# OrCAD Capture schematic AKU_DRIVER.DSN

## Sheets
1 CHARGER: size A4; title: Pb-accu driver - Charger; rev: A; note: Pb-accu_driver_01
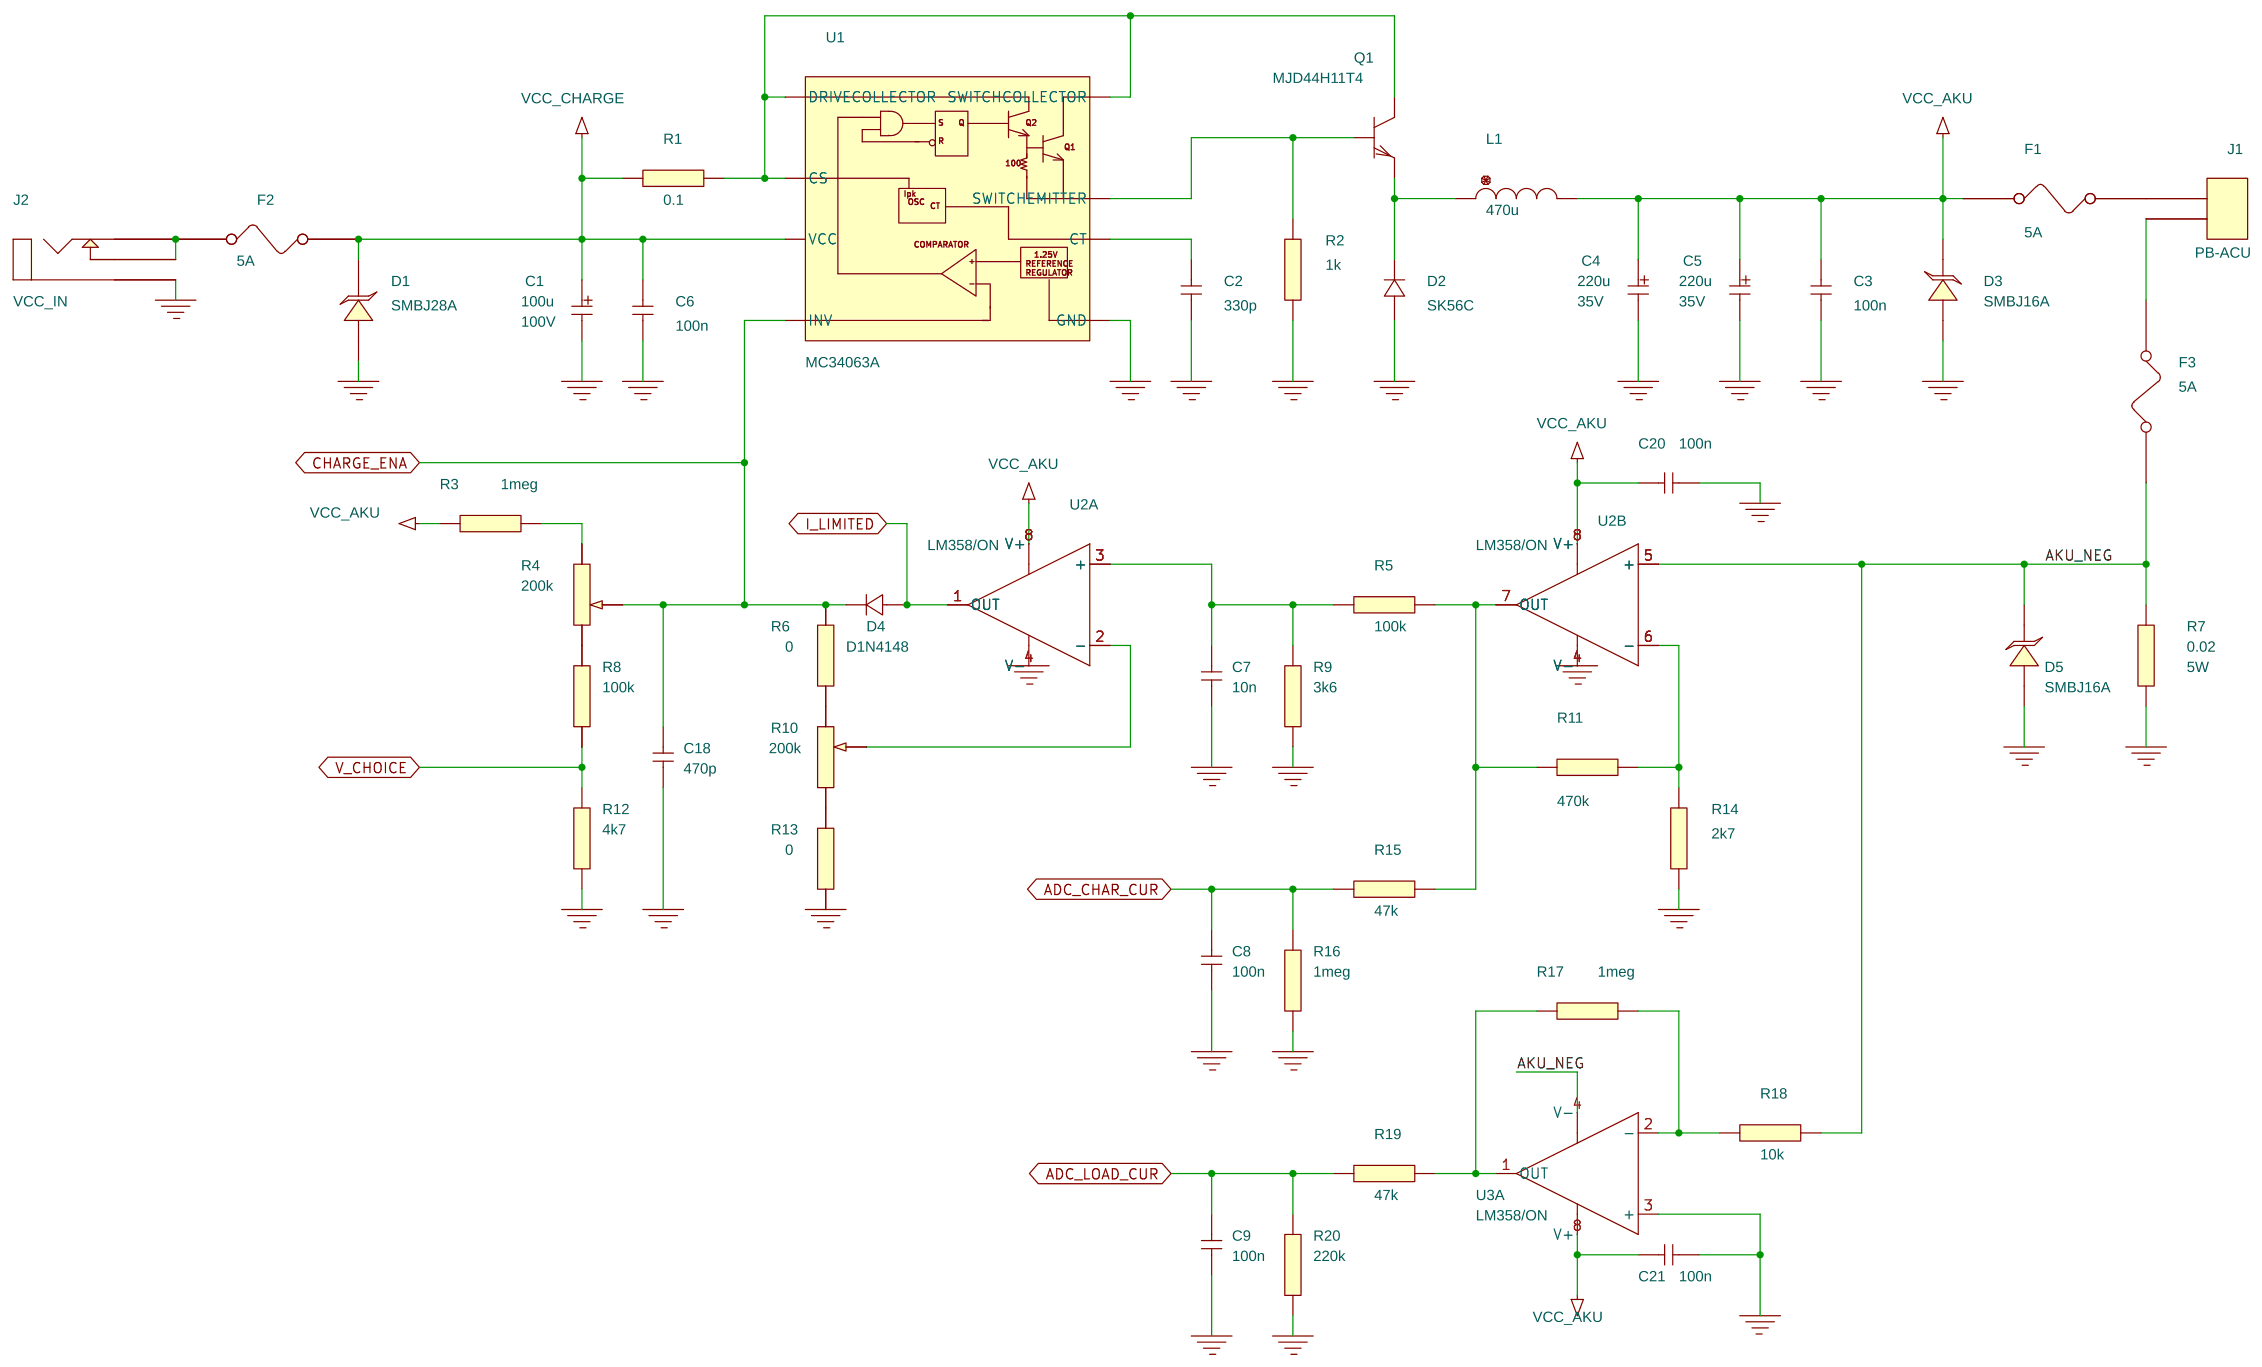
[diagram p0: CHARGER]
2 POWER: size A4; title: Pb-accu driver - Power and Load; note: Pb-accu_driver_03
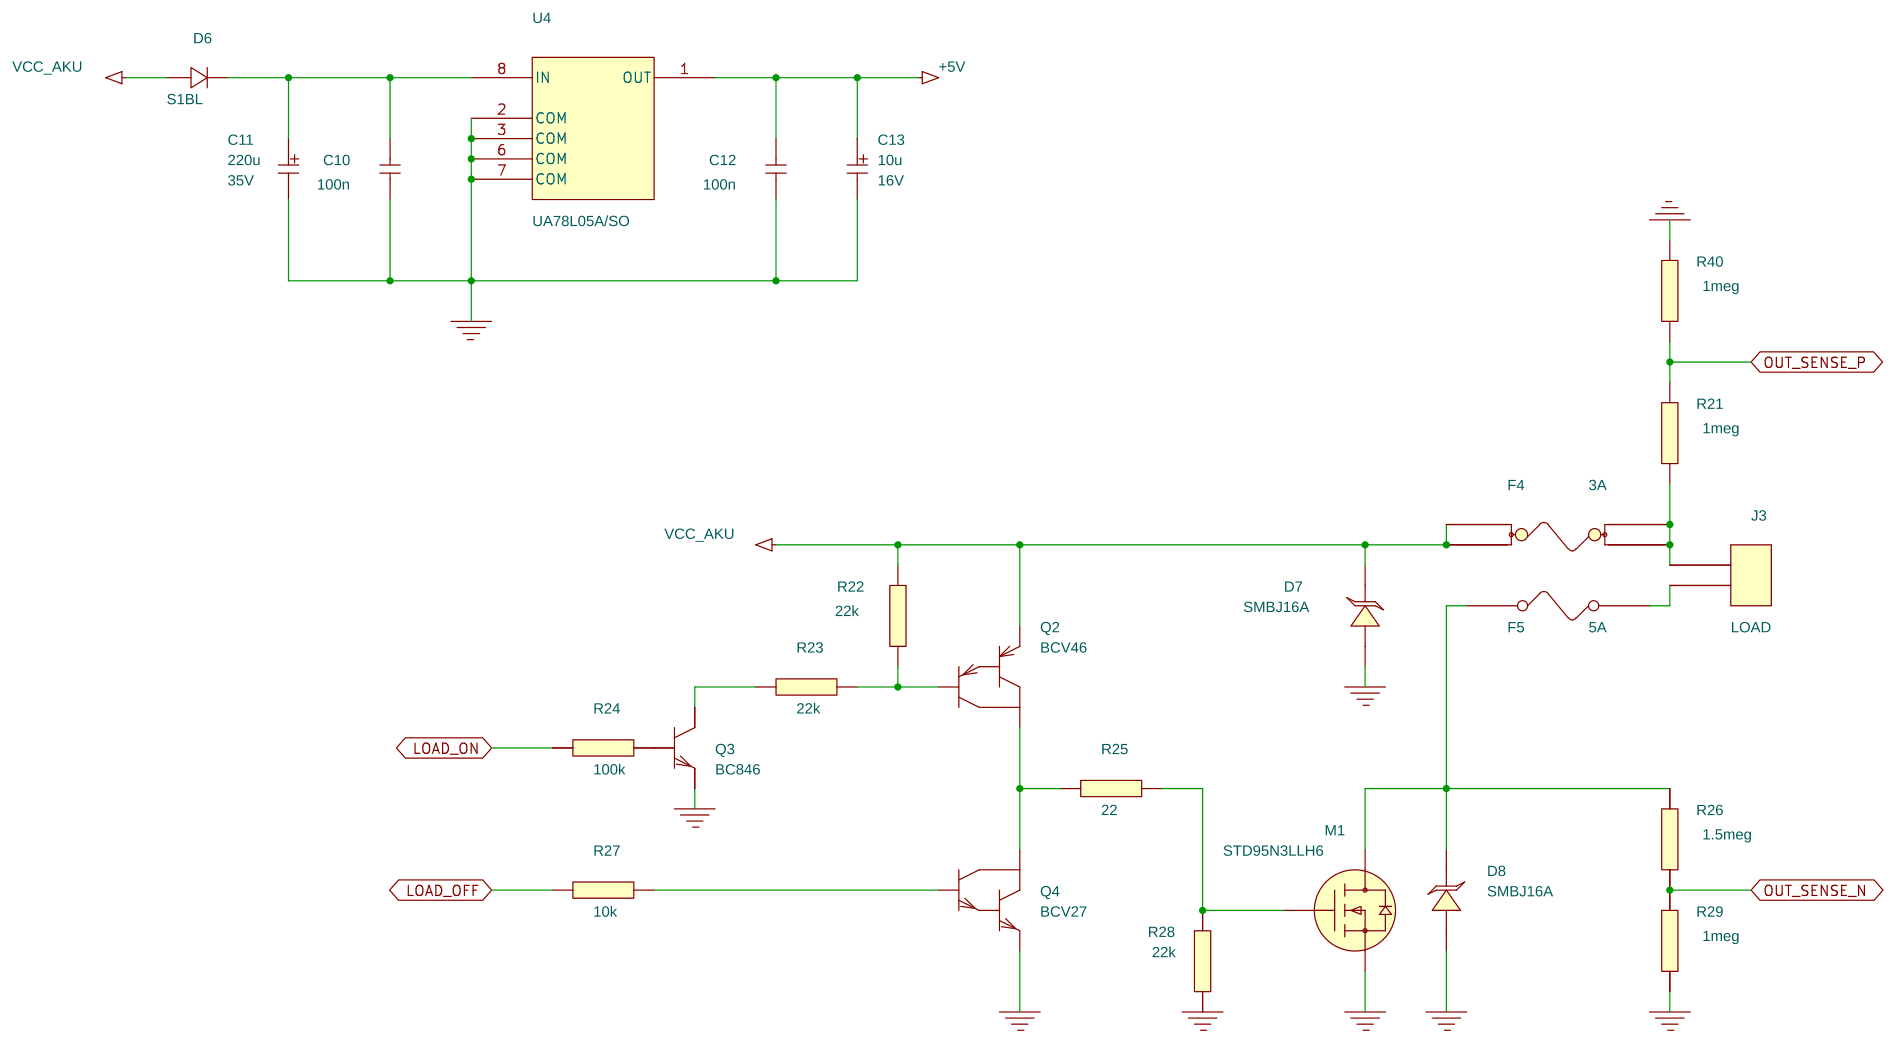
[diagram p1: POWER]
3 PROCESSOR: size A4; title: Pb-accu driver - MCU and LCD; note: Pb-accu_driver_02
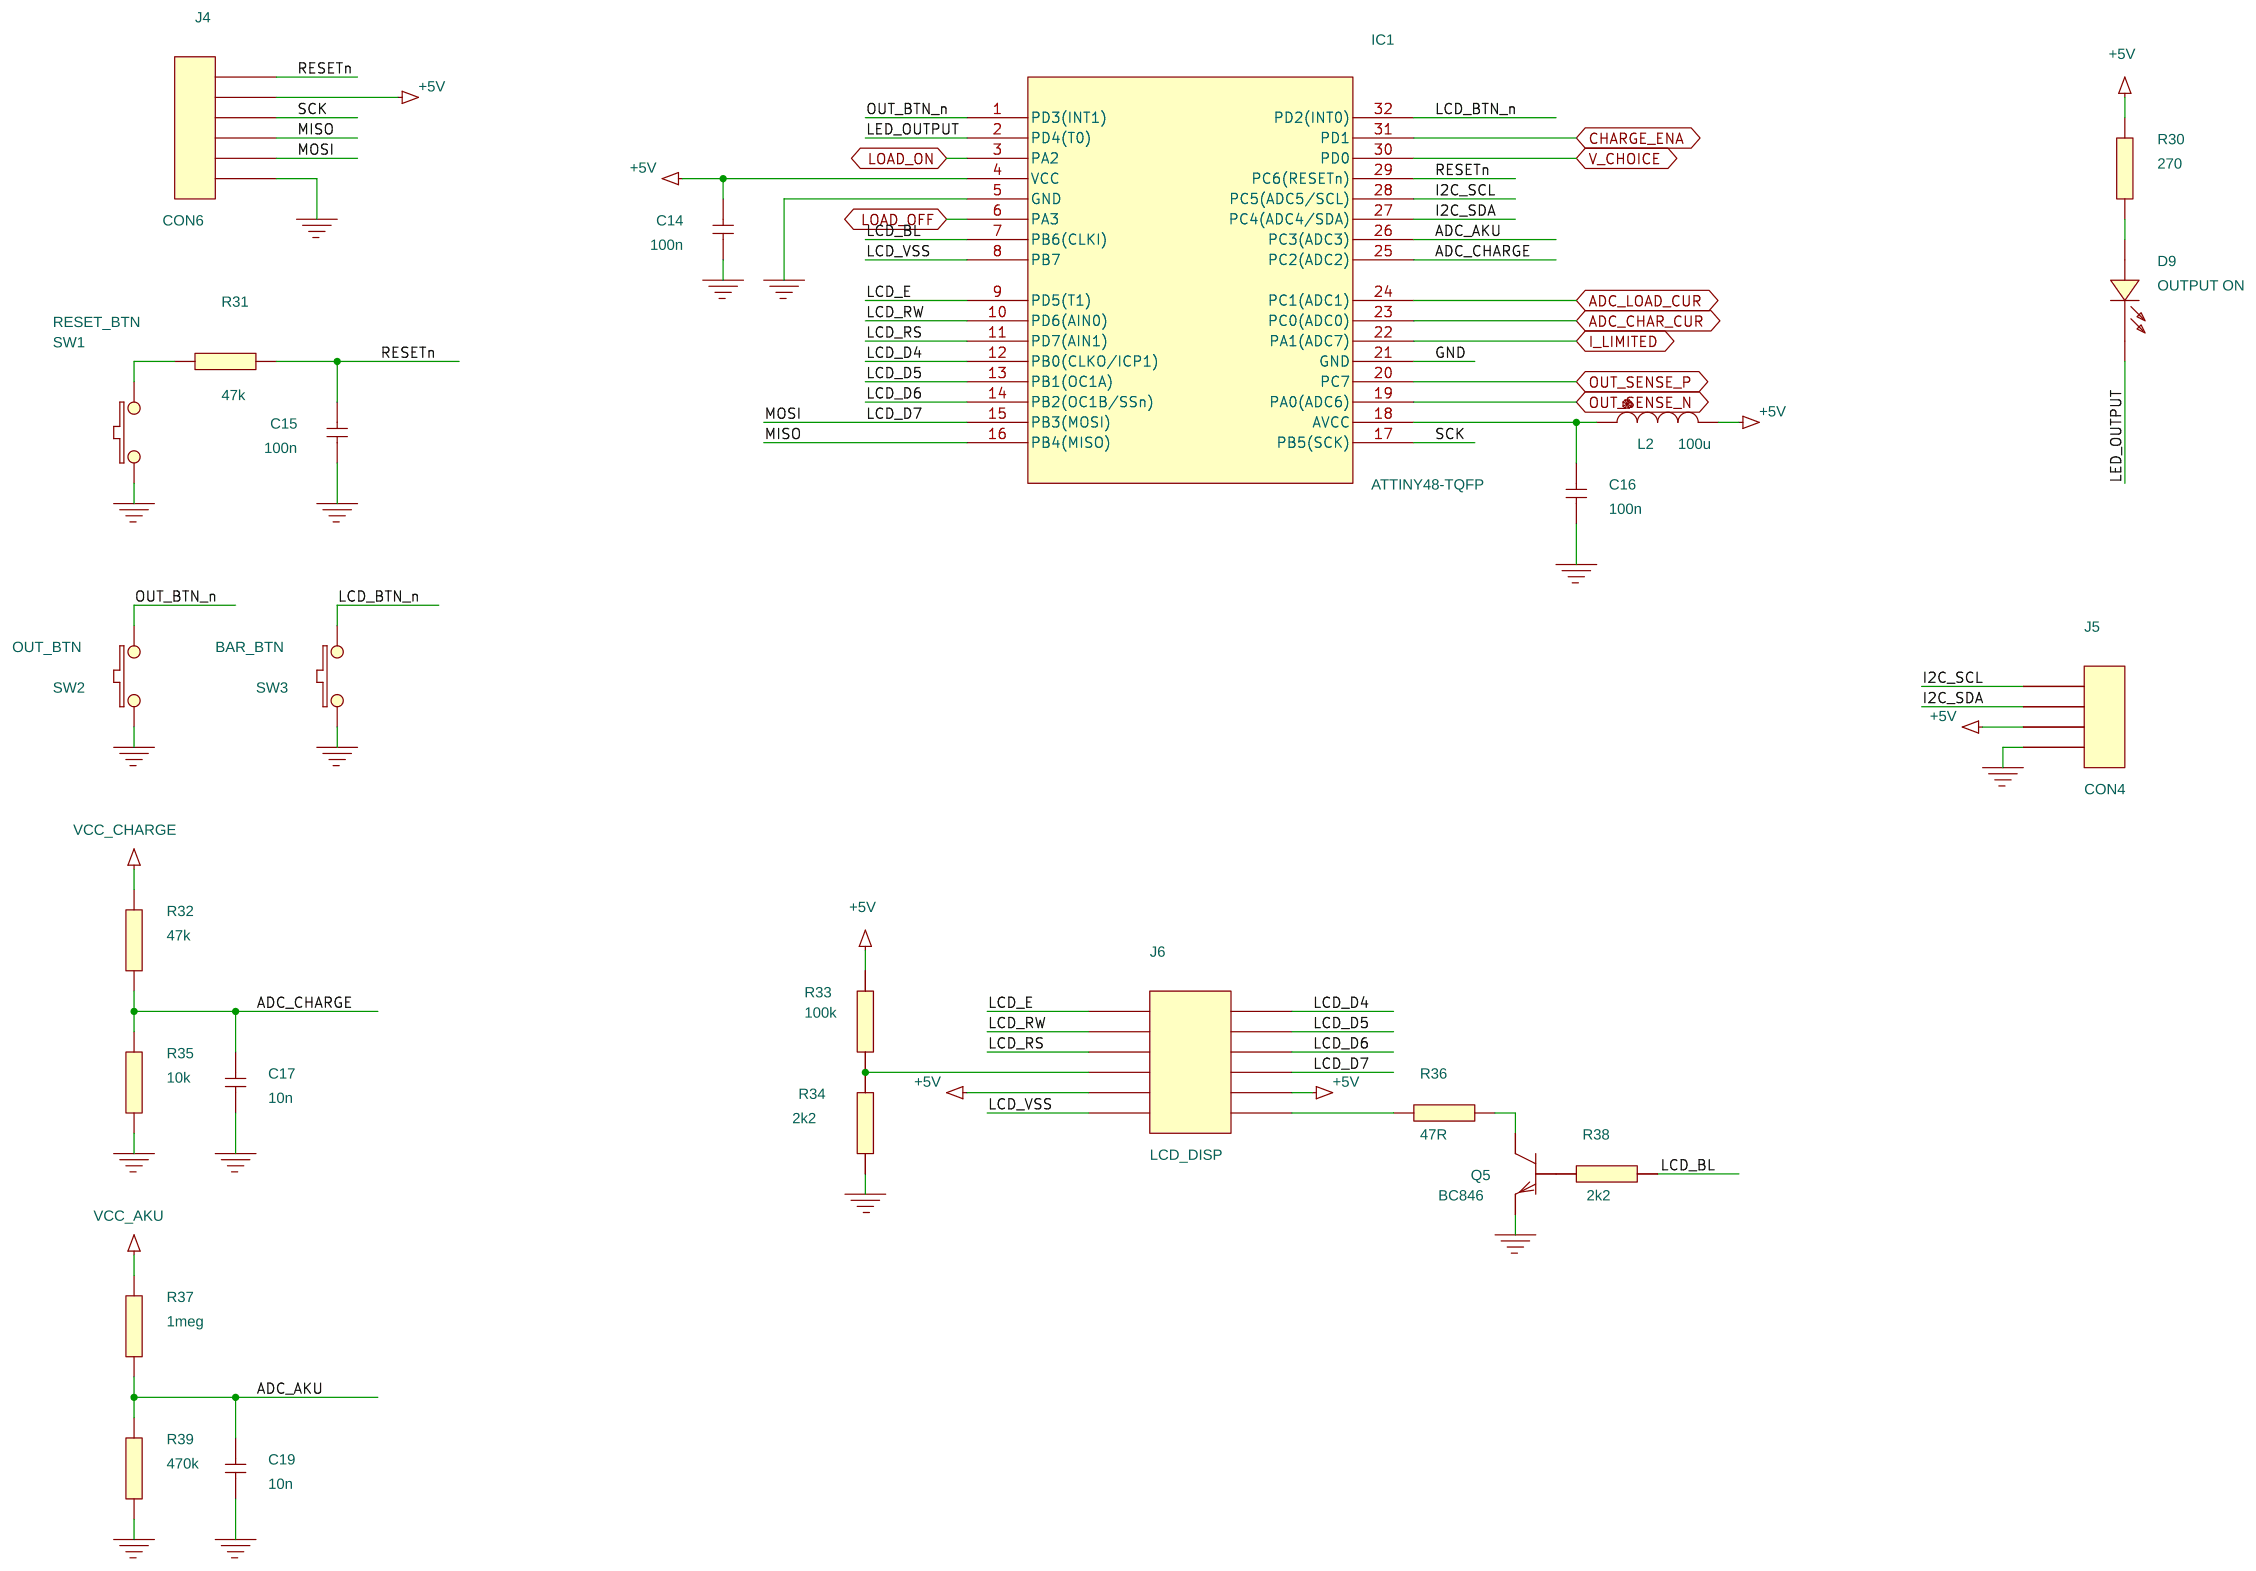
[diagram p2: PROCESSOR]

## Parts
sheet CHARGER
C1  100u  [CPCYL/D.400/LS.200/.034]
C2  330p  [SM/C_0805]
C3  100n  [SM/C_0805]
C4  220u  [CPCYL/D.325/LS.175/.034]
C5  220u  [CPCYL/D.325/LS.175/.034]
C6  100n  [SM/C_0805]
C7  10n  [SM/C_0805]
C8  100n  [SM/C_0805]
C9  100n  [SM/C_0805]
C18  470p  [SM/C_0805]
C20  100n  [SM/C_0805]
C21  100n  [SM/C_0805]
D1  SMBJ28A  [SM/DO214AA_21]
D2  SK56C  [SM/DO214AB_12]
D3  SMBJ16A  [SM/DO214AA_21]
D4  D1N4148  [SM/D_1206_21]
D5  SMBJ16A  [SM/DO214AA_21]
F1  5A  [FUSE1508]
F2  5A  [FUSE1508]
F3  5A  [FUSE1508]
J1  PB-ACU  [KONEKTOR 5.08MM/2]
J2  VCC_IN  [POWER_JACK]
L1  470u  [PULSE_P1945]
Q1  MJD44H11T4  [TO252AA/DPAK]
R1  0.1  [SM/R_0805]
R2  1k  [SM/R_0805]
R3  1meg  [SM/R_0805]
R4  200k  [TRIMMER_3006P]
R5  100k  [SM/R_0805]
R6  0  [SM/R_0805]
R7  0.02  [R_BRIDGE_5W]
R8  100k  [SM/R_0805]
R9  3k6  [SM/R_0805]
R10  200k  [TRIMMER_3006P]
R11  470k  [SM/R_0805]
R12  4k7  [SM/R_0805]
R13  0  [SM/R_0805]
R14  2k7  [SM/R_0805]
R15  47k  [SM/R_0805]
R16  1meg  [SM/R_0805]
R17  1meg  [SM/R_0805]
R18  10k  [SM/R_0805]
R19  47k  [SM/R_0805]
R20  220k  [SM/R_0805]
U1  MC34063A  [SOG.050/8/WG.244/L.200]
U2  LM358/ON  [SOG.050/8/WG.244/L.200]  (sections A,B)
U3  LM358/ON  [SOG.050/8/WG.244/L.200]  (section A)
sheet POWER
C10  100n  [SM/C_0805]
C11  220u  [CPCYL/D.325/LS.175/.034]
C12  100n  [SM/C_0805]
C13  10u  [SM/CT_3216]
D6  S1BL  [SUB_SMA]
D7  SMBJ16A  [SM/DO214AA_21]
D8  SMBJ16A  [SM/DO214AA_21]
F4  3A  [FUSE]
F5  5A  [FUSE1508]
J3  LOAD  [KONEKTOR 5.08MM/2]
M1  STD95N3LLH6  [TO252AA/DPAK]
Q2  BCV46  [SM/SOT23_BEC]
Q3  BC846  [SM/SOT23_BEC]
Q4  BCV27  [SM/SOT23_BEC]
R21  1meg  [SM/R_0805]
R22  22k  [SM/R_0805]
R23  22k  [SM/R_0805]
R24  100k  [SM/R_0805]
R25  22  [SM/R_0805]
R26  1.5meg  [SM/R_0805]
R27  10k  [SM/R_0805]
R28  22k  [SM/R_0805]
R29  1meg  [SM/R_0805]
R40  1meg  [SM/R_0805]
U4  UA78L05A/SO  [SOG.050/8/WG.244/L.200]
sheet PROCESSOR
C14  100n  [SM/C_0805]
C15  100n  [SM/C_0805]
C16  100n  [SM/C_0805]
C17  10n  [SM/C_0805]
C19  10n  [SM/C_0805]
D9  OUTPUT ON  [BLKCON.100/VH/TM1SQS/W.100/2]
IC1  ATTINY48-TQFP  [QUAD.80M/32/WG9.00]
J4  CON6  [BLKCON.100/VH/TM1SQ/W.100/6]
J5  CON4  [BLKCON.100/VH/TM1SQ/W.100/4]
J6  LCD_DISP  [BLKCON.100/VH/TM2OE/W.200/12]
L2  100u  [SM/L_1210]
Q5  BC846  [SM/SOT23_BEC]
R30  270  [SM/R_0805]
R31  47k  [SM/R_0805]
R32  47k  [SM/R_0805]
R33  100k  [SM/R_0805]
R34  2k2  [SM/R_0805]
R35  10k  [SM/R_0805]
R36  47R  [SM/R_0805]
R37  1meg  [SM/R_0805]
R38  2k2  [SM/R_0805]
R39  470k  [SM/R_0805]
SW1  RESET_BTN  [BLKCON.100/VH/TM1SQS/W.100/2]
SW2  OUT_BTN  [BLKCON.100/VH/TM1SQS/W.100/2]
SW3  BAR_BTN  [BLKCON.100/VH/TM1SQS/W.100/2]

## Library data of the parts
C1 = C_elect: COMPGROUP: 0; Voltage: 100V
C2 C3 C6 = C: COMPGROUP: 0
C4 C5 = C_elect: COMPGROUP: 0; Voltage: 35V
C7 C8 C18 = C: COMPGROUP: 3
C9 C20 C21 = C: COMPGROUP: 4
D1 = DIODE_TVS: COMPGROUP: 1
D2 = D1N5822: COMPGROUP: 0
D3 = DIODE_TVS
D4 = 1N4148: COMPGROUP: 3
D5 = DIODE_TVS: COMPGROUP: 2
F1 F3 = FUSE: COMPGROUP: 2
F2 = FUSE: COMPGROUP: 1
J1 = CON2: COMPGROUP: 2
J2 = CONN_JACK_PWR: COMPGROUP: 1
L1 = L: COMPGROUP: 0
Q1 = PZTA42_INF_0: COMPGROUP: 0
R1 R2 = R: COMPGROUP: 0
R3 R5 R6 R8 R9 R11-R16 = R: COMPGROUP: 3
R4 R10 = POT_0: COMPGROUP: 3
R7 = R: COMPGROUP: 2; POWER: 5W
R17-R20 = R: COMPGROUP: 4
U1 = MC34063A: COMPGROUP: 0
U2 = LM358_ON: COMPGROUP: 3
U3 = LM358_ON: COMPGROUP: 4
C10 = C: COMPFIXED: NO; COMPGROUP: 11; COMPHEIGHT: 0.000; COMPKEY: NO; COMPLOC: [6270.000,2676.000]; COMPLOCKED: NO; COMPROT: 0; COMPSIDE: BOT; DECOUPLER: NO; FPLIST: SM/C_1206; MEMORY: NO
C11 = C_elect: COMPFIXED: NO; COMPGROUP: 11; COMPHEIGHT: 0.000; COMPKEY: NO; COMPLOC: [6210.000,2562.000]; COMPLOCKED: NO; COMPROT: 90; COMPSIDE: TOP; DECOUPLER: NO; FPLIST: SM/CT_7343; MEMORY: NO; Voltage: 35V
C12 = C: COMPFIXED: NO; COMPGROUP: 11; COMPHEIGHT: 0.000; COMPKEY: NO; COMPLOC: [5802.000,2904.000]; COMPLOCKED: NO; COMPROT: 0; COMPSIDE: BOT; DECOUPLER: NO; FPLIST: SM/C_1206; MEMORY: NO
C13 = C_elect: COMPFIXED: NO; COMPGROUP: 11; COMPHEIGHT: 0.000; COMPKEY: NO; COMPLOC: [5718.000,2778.000]; COMPLOCKED: NO; COMPROT: 90; COMPSIDE: BOT; DECOUPLER: NO; MEMORY: NO; Voltage: 16V
D6 = D1N4001: COMPFIXED: NO; COMPGROUP: 11; COMPHEIGHT: 0.000; COMPKEY: NO; COMPLOC: [6480.000,2562.000]; COMPLOCKED: NO; COMPROT: 180; COMPSIDE: BOT; DECOUPLER: NO; FPLIST: SM/DO214AA_21,SM/DO214AA_12,SM/D_1406_12,KONEKTOR 5MM/7; MEMORY: NO
D7 D8 = DIODE_TVS: COMPGROUP: 12
F4 = FUSE4PIN_2: COMPGROUP: 12
F5 = FUSE: COMPGROUP: 12
J3 = CON2: COMPGROUP: 12
M1 = IRLR110_0: COMPGROUP: 12
Q2 = BCV46_PLP_0: COMPGROUP: 13
Q3 = BC846_INF: COMPGROUP: 13
Q4 = BCV27_PLP_0: COMPGROUP: 13
R21 R26 R29 R40 = R: COMPGROUP: 12
R22-R25 R27 R28 = R: COMPGROUP: 13
U4 = UA78L05A_SO_0: COMPFIXED: NO; COMPGROUP: 11; COMPHEIGHT: 0.000; COMPKEY: NO; COMPLOC: [5880.000,2682.000]; COMPLOCKED: NO; COMPROT: 270; COMPSIDE: BOT; DECOUPLER: NO; FPLIST: SOG.050/8/WG.244/L.175; MEMORY: NO
C14 C16 = C: COMPGROUP: 5
C15 = C: COMPGROUP: 8
C17 = C: COMPGROUP: 9
C19 = C: COMPGROUP: 10
D9 = LED: COMPGROUP: 7
IC1 = ATTINY48-TQFP_0: COMPGROUP: 5
J4 = CON6: COMPFIXED: NO; COMPGROUP: 0; COMPHEIGHT: 0.000; COMPKEY: NO; COMPLOC: [5216.083,1771.500]; COMPLOCKED: NO; COMPROT: 0; COMPSIDE: TOP; DECOUPLER: NO; MEMORY: NO
J5 = CON4
J6 = CON12A
L2 = L: COMPGROUP: 5
Q5 = BC846_INF: COMPGROUP: 6
R30 = R: COMPGROUP: 7
R31 = R: COMPGROUP: 8
R32 R35 = R: COMPGROUP: 9
R33 R34 R36 R38 = R: COMPGROUP: 6
R37 R39 = R: COMPGROUP: 10
SW1 = SW_PUSHBUTTON: COMPGROUP: 8
SW2 SW3 = SW_PUSHBUTTON

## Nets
+5V: C12.2 C13.P(+) C14.2 IC1.4(VCC) J4.2 J5.3 J6.3 J6.4 L2.2 R30.1 R33.1 U4.1(OUT)
GND: C1.N(-) C2.1 C3.1 C4.N(-) C5.N(-) C6.1 C7.1 C8.1 C9.1 C10.1 C11.N(-) C12.1 C13.N(-) C14.1 C15.1 C16.1 C17.1 C18.1 C19.1 C20.1 C21.1 D1.1(ANODE) D2.2(1) D3.1(ANODE) D5.1(ANODE) D7.1(ANODE) D8.1(ANODE) IC1.5(GND) IC1.21(GND) J2.1 J4.6 J5.4 M1.3(S) Q3.e Q4.E(e) Q5.e R2.1 R7.1 R9.1 R12.1 R13.1 R14.1 R16.1 R20.1 R28.1 R29.2 R34.2 R35.2 R39.2 R40.1 SW1.2 SW2.2 SW3.2 U1.4(GND) U2.4(V-) U3.3(+) U4.2(COM) U4.3(COM) U4.6(COM) U4.7(COM)
VCC_AKU: C3.2 C4.P(+) C5.P(+) C20.2 C21.2 D3.2(CATHODE) D6.1 D7.2(CATHODE) F1.2 F4.1 F4.3 L1.2 Q2.E(e) R3.1 R22.1 R37.1 U2.8(V+) U3.8(V+)
VCC_CHARGE: C1.P(+) C6.2 D1.2(CATHODE) F2.2 R1.1 R32.1 U1.6(VCC)
ADC_AKU: C19.2 IC1.26(PC3(ADC3)) R37.2 R39.1
ADC_CHAR_CUR: C8.2 IC1.23(PC0(ADC0)) R15.1 R16.2
ADC_CHARGE: C17.2 IC1.25(PC2(ADC2)) R32.2 R35.1
ADC_LOAD_CUR: C9.2 IC1.24(PC1(ADC1)) R19.1 R20.2
AKU_NEG: D5.2(CATHODE) F3.2 R7.2 R18.2 U2.5(+) U3.4(V-)
CHARGE_ENA: C18.2 D4.2 IC1.31(PD1) R4.2 R6.2 U1.5(INV)
I2C_SCL: IC1.28(PC5(ADC5/SCL)) J5.1
I2C_SDA: IC1.27(PC4(ADC4/SDA)) J5.2
I_LIMITED: D4.1 IC1.22(PA1(ADC7)) U2.1(OUT)
LCD_BL: IC1.7(PB6(CLKI)) R38.2
LCD_BTN_n: IC1.32(PD2(INT0)) SW3.1
LCD_D4: IC1.12(PB0(CLKO/ICP1)) J6.12
LCD_D5: IC1.13(PB1(OC1A)) J6.10
LCD_D6: IC1.14(PB2(OC1B/SSn)) J6.8
LCD_D7: IC1.15(PB3(MOSI)) J4.5 J6.6
LCD_E: IC1.9(PD5(T1)) J6.11
LCD_RS: IC1.11(PD7(AIN1)) J6.7
LCD_RW: IC1.10(PD6(AIN0)) J6.9
LCD_VSS: IC1.8(PB7) J6.1
LED_OUTPUT: D9.2(CATHODE) IC1.2(PD4(T0))
LOAD_OFF: IC1.6(PA3) R27.2
LOAD_ON: IC1.3(PA2) R24.2
MISO: IC1.16(PB4(MISO)) J4.4
OUT_BTN_n: IC1.1(PD3(INT1)) SW2.1
OUT_SENSE_N: IC1.19(PA0(ADC6)) R26.2 R29.1
OUT_SENSE_P: IC1.20(PC7) R21.1 R40.2
RESETn: C15.2 IC1.29(PC6(RESETn)) J4.1 R31.2
SCK: IC1.17(PB5(SCK)) J4.3
V_CHOICE: IC1.30(PD0) R8.1 R12.2
N05927: C2.2 U1.3(CT)
N05973: D2.1(2) L1.1 Q1.3(e)
N06157: Q1.4(c) R1.2 U1.1(SWITCHCOLLECTOR) U1.7(CS) U1.8(DRIVECOLLECTOR)
N06313: R11.2 R14.2 U2.6(-)
N06353: R5.2 R11.1 R15.2 U2.7(OUT)
N06567: R10.2 U2.2(-)
N06653: C7.2 R5.1 R9.2 U2.3(+)
N08184: Q1.1(b) R2.2 U1.2(SWITCHEMITTER)
N8620741: F2.1 J2.2 J2.3
N8622718: F3.1 J1.1
N8624204: D8.2(CATHODE) F5.1 M1.4(D) R26.1
N9293320: M1.1(G) R25.1 R28.2
N9293532: Q2.C(c) Q4.C(c) R25.2
N9293586: Q3.c R23.2
N9293597: Q2.B(b) R22.2 R23.1
N9293828: Q4.B(b) R27.1
N9329787: C10.2 C11.P(+) D6.2 U4.8(IN)
N9331225: R31.1 SW1.1
N9332629: C16.2 IC1.18(AVCC) L2.1
N9334200: D9.1(ANODE) R30.2
N9337199: F5.2 J3.1
N9337317: F4.2 F4.4 J3.2 R21.2
N9340983: Q5.c R36.2
N9371123: R17.2 R18.1 U3.2(-)
N9371344: R17.1 R19.2 U3.1(OUT)
N9375482: R3.2 R4.3
N9385546: R10.3 R13.2
N9385547: R6.1 R10.1
N9385745: Q3.b R24.1
N9389144: J6.5 R33.2 R34.1
N9391537: J6.2 R36.1
N9393602: Q5.b R38.1
N9395491: R4.1 R8.2
N9395911: F1.1 J1.2
